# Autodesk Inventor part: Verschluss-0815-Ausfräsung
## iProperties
Manager: Dr.-Ing. Roland Schröder
Company: www.Das-Entwicklungsbuero.de
Created: 2006-09
Part Number: Verschluss-0815-Ausfräsung
Project: 12107
Document SubType Name: Modeling
Designer: rsc
Engineer: Dr.-Ing. Roland Schröder
b: 50,000 mm
d: 30,000 mm
a: 10,000 mm
Kanten: brechen
Oberflächen: Ra 6,4
Toleranzen: ISO 2768 - m
Author: rsc
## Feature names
1. Extrusion2
2. Rundung1 [Fillet]
3. Flansch [Extrusion]
4. Fase1 [Chamfer]
5. Bohrungen [Extrusion]
6. Spiegeln1 [Mirror]
7. Spiegeln2 [Mirror]
